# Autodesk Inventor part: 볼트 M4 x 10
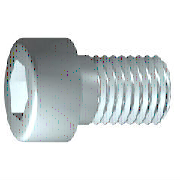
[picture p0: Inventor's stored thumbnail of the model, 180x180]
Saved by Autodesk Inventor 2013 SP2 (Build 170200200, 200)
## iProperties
IsCustomPart: 0
Created: 2012-02
Part Number: 볼트 M4 x 10
Material: 강철, 연강
Description: 6각 소켓 머리 캡 나사
Document SubType Name: Modeling
Standard: ISO 4762
Designer: mduedu
Standard Revision: Fourth edition 2004-03-01
Standards Organization: ISO
Language: ko-KR
Size Designation: M4 x 12
Categories: <MemberInstance><Categories><Category DisplayName="조임쇠" InternalName="e4da775c-781d-43d5-af7c-5136215cf5a6" Mnemonic="FSTN"><Category DisplayName="볼트" InternalN
Density: 7.75 g/cm^3
Author: mduedu
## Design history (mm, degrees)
sketch "스케치1"
  geometry: L1 (-1, 0)-(10, 0); L2 (10, 0)-(10, 2); L3 (10, 2)-(1.75, 2); L4 (1.75, 2)-(1.32, 2); L5 (1.32, 2)-(0, 2); L6 (0, 2)-(0, 3.5); L7 (0, 3.5)-(-4, 3.5); L8 (-4, 3.5)-(-4, 1.732); L9 (-4, 1.732)-(-2, 1.732); L10 (-2, 1.732)-(-1, 0); L11 (-7.2, 0)-(15.2, 0) reference; L12 (0, -0.7)-(0, 4.2) reference; L13 (1.75, 2)-(0, 2)
  constraints: 22 end point, 6 parallel, 2 collinear, 2 perpendicular, 1 horizontal, 1 point on line
  dimensions: "d1" = 8.25 distance from line of L3.end L2 (= GEL); "d2" = 0.42952 distance of L4.end L3.end (computed from GAL); "d3" = 4 distance between parallel lines of L8 L6 (= KOH); "d4" = 2 distance of L8.end L9.end (= INTI); "d5" = 60 deg angle of L10 L1; "d6" = 4 diameter of L3 L1 (= GD); "d7" = 4 diameter of L5 L1 (= BDM); "d8" = 3.4641 diameter of L9 L1 (= 1.1547 x SW); "d9" = 7 diameter of L7 L1 (= KOD); "d26" = 10 distance between parallel lines of L12 L2 (= NLG)
revolve "본체" sketch "스케치1" stored, may be unused: angle "d10" = 90 deg
sketch "스케치2"
  geometry: L1 (0, -4.9)-(0, 4.9) reference; L2 (-4.9, 0)-(4.9, 0) reference; L3 (1.732, 0)-(0.866, -1.5); L4 (0.866, -1.5)-(-0.866, -1.5); L5 (-0.866, -1.5)-(-1.732, 0); L6 (-1.732, 0)-(-0.866, 1.5); L7 (-0.866, 1.5)-(0.866, 1.5); L8 (0.866, 1.5)-(1.732, 0); 2 further points
  constraints: 12 end point, 1 coincident, 1 horizontal alignment, 1 point on line, 12 other
extrude "슬롯" join sketch "스케치2" stored distance "d11" = 10; taper "d12" = 0 deg
workplane "Work Plane1"
fillet "Fillet2" dims "d30" = 0.1 (= R)
body "Solid1"
fillet "모깎기1" dims "d17" = 0.4 (= RR)
feature "스레드" dims "d13" = 8.25 (= GEL), "d14" = 0
chamfer "모따기1" distance "d15" = 0.42941 (= -0.5 x SPD + 0.5 x GD); stored, may be unused: second distance "d16" = 0.42941 (= GUL), angle "d27" = 45 deg
other parameters: "GD" = 4 [user parameter; used in 2 equation terms], "NLG" = 10 [user parameter; used in 1 equation term], "GEL" = 8.25 [user parameter; used in 2 equation terms], "KOD" = 7 [user parameter; used in 1 equation term], "KOH" = 4 [user parameter; used in 1 equation term], "INTI" = 2 [user parameter; used in 1 equation term], "GAL" = 0.42941 (= 0.61345 x PTC) [user parameter; used in 1 equation term], "GUL" = 0.42941 (= 0.61345 x PTC) [user parameter; used in 1 equation term], "BDM" = 4 (= NND) [user parameter; used in 1 equation term], "SW" = 3 [user parameter; used in 2 equation terms], "RR" = 0.4 [user parameter; used in 1 equation term], "SPD" = 3.14117 (= NND - 1.2269 x PTC) [user parameter; used in 1 equation term], "d19" = 0, "d28" = 0, "d29" = 0, "R" = 0.1 [user parameter; used in 1 equation term], "TOA" = 30 deg [user parameter], "GD1" = 3.14117 (= THREADDIA - 1.2269 x PTC) [user parameter], "THREADDIA" = 4 [user parameter; used in 1 equation term], "FAWI" = 45 deg [user parameter], "TPU" = 14.28571 (computed from PTC) [user parameter], "PTC" = 0.7 [user parameter; used in 5 equation terms], "NND" = 4 [user parameter; used in 2 equation terms], "E0" = 3.465 (= 1.155 x SW) [user parameter]
